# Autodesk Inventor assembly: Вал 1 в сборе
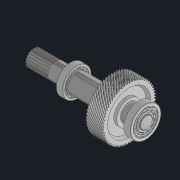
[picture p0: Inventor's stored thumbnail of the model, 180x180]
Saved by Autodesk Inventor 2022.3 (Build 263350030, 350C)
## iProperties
Created: 2022-08
Part Number: Вал 1 в сборе
Document SubType Name: Assembly
Designer: Карташов
Author: Карташов
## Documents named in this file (7)
- C:\Users\wsr\Desktop\Новая папка\10. Редуктор\Вал 1 в сборе.iam
- C:\Users\wsr\Desktop\Новая папка\10. Редуктор\Вал 1.ipt
- C:\Users\wsr\Desktop\Новая папка\10. Редуктор\GIVEN\Шпонка ISO 2491 22x9-63-A.ipt
- C:\Users\wsr\Desktop\Новая папка\10. Редуктор\GIVEN\Шестерня 2.ipt
- C:\Users\wsr\Desktop\Новая папка\10. Редуктор\GIVEN\Стопорное кольцо DIN 471 - 80 x 4.ipt
- C:\Users\wsr\Desktop\Новая папка\10. Редуктор\GIVEN\ISO 15 - 60 x 150 x 35.ipt
- C:\Users\wsr\Desktop\Новая папка\10. Редуктор\GIVEN\ISO 15 - 80 x 140 x 33.ipt
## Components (6 placed, 6 different names)
1. Вал 1:1 — Совмещение:1, Совмещение:2, Совмещение:3, Совмещение:4, Совмещение:6, Совмещение:7, С поворотом:1, С поворотом:2
2. Шпонка ISO 2491 22x9-63-A:1 — Совмещение:2, Совмещение:3, Совмещение:4, Совмещение:5
3. Шестерня 2:1 — Совмещение:1, Совмещение:5, Совмещение:6, Совмещение:8
4. Стопорное кольцо DIN 471 - 80 x 4:1 — Совмещение:7, Совмещение:8
5. ISO 15 - 60 x 150 x 35:1 — С поворотом:2
6. ISO 15 - 80 x 140 x 33:1 — С поворотом:1
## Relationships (10: Mate 8, RevoluteJoint 2)
- Совмещение:1 [Mate]: Вал 1:1 ↔ Шестерня 2:1
- Совмещение:2 [Mate]: Вал 1:1 ↔ Шпонка ISO 2491 22x9-63-A:1
- Совмещение:3 [Mate]: Вал 1:1 ↔ Шпонка ISO 2491 22x9-63-A:1
- Совмещение:4 [Mate]: Вал 1:1 ↔ Шпонка ISO 2491 22x9-63-A:1
- Совмещение:5 [Mate]: Шпонка ISO 2491 22x9-63-A:1 ↔ Шестерня 2:1
- Совмещение:6 [Mate]: Вал 1:1 ↔ Шестерня 2:1
- Совмещение:7 [Mate]: Вал 1:1 ↔ Стопорное кольцо DIN 471 - 80 x 4:1
- Совмещение:8 [Mate]: Шестерня 2:1 ↔ Стопорное кольцо DIN 471 - 80 x 4:1
- С поворотом:1 [RevoluteJoint]: Вал 1:1 ↔ ISO 15 - 80 x 140 x 33:1
- С поворотом:2 [RevoluteJoint]: Вал 1:1 ↔ ISO 15 - 60 x 150 x 35:1
